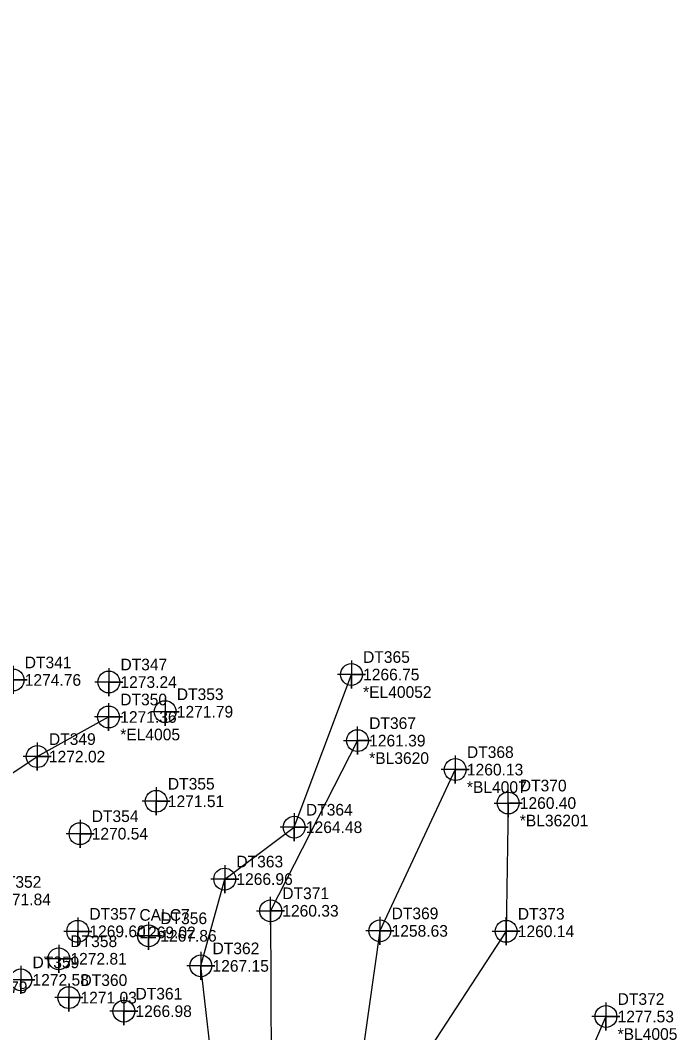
# Model space of a CAD drawing. Extents: x 1391270 to 1392151, y 960049 to 960667.
# Drawn here: x 1391544.4 to 1391685.2, y 960444.8 to 960661.8 of the extents above; entities that cross this region are included whole.
import ezdxf

# ---------------------------------------------------------------- set-up
doc = ezdxf.new("R2010")
doc.units = 0
for name, color, linetype in [('COGO Default Point Elevation', 7, 'Continuous'), ('COGO Default Point Number', 7, 'Continuous'), ('Exist DTM Breakline', 7, 'Continuous'), ('Exist DTM Breakline Cogo Comment', 7, 'Continuous'), ('Exist DTM Breakline Cogo Elevation', 7, 'Continuous'), ('Exist DTM Breakline Cogo Number', 7, 'Continuous'), ('Exist DTM Breakline Cogo Point CELL', 7, 'Continuous'), ('Exist DTM Breakline Underwater', 7, 'Continuous'), ('Exist DTM Breakline Underwater Cogo Comment', 7, 'Continuous'), ('Exist DTM Breakline Underwater Cogo Elevation', 7, 'Continuous'), ('Exist DTM Breakline Underwater Cogo Number', 7, 'Continuous'), ('Exist DTM Breakline Underwater Cogo Point CELL', 7, 'Continuous'), ('Exist DTM Regular Point CELL', 7, 'Continuous'), ('Exist DTM Regular Point Cogo Elevation', 7, 'Continuous'), ('Exist DTM Regular Point Cogo Number', 7, 'Continuous'), ('Exist Hydro Stream or Body of Water', 7, 'Continuous'), ('Exist Hydro Stream or Body of Water Cogo Comment', 7, 'Continuous'), ('Exist Hydro Stream or Body of Water Cogo Elevation', 7, 'Continuous'), ('Exist Hydro Stream or Body of Water Cogo Number', 7, 'Continuous'), ('Exist Hydro Stream or Body of Water Cogo Point CELL', 7, 'Continuous'), ('Exist Roads EOP', 7, 'Continuous')]:
    doc.layers.add(name, color=color, linetype=linetype)

msp = doc.modelspace()

# ---------------------------------------------------------------- linework, layer by layer
at = {"layer": 'Exist DTM Breakline'}
msp.add_line((1391670.034, 960448.283), (1391658.104, 960420.856), dxfattribs=at)
for points in [[(1391393.449, 960661.814), (1391420.927, 960625.274), (1391436.139, 960609.727), (1391454.255, 960579.709), (1391474.064, 960542.237), (1391491.205, 960517.974), (1391488.925, 960510.22), (1391503.285, 960493.748), (1391518.522, 960484.392), (1391548.09, 960503.995), (1391563.385, 960512.482)], [(1391572.183, 960404.498), (1391585.5, 960391.636), (1391586.242, 960432.256), (1391583.174, 960459.141), (1391588.288, 960477.745), (1391603.196, 960488.857), (1391615.455, 960521.583)]]:
    msp.add_lwpolyline(points, dxfattribs=at)
at = {"layer": 'Exist DTM Breakline Cogo Point CELL'}
for points in [[(1391615.455, 960524.583), (1391615.455, 960518.583), (1391615.455, 960521.583), (1391618.455, 960521.583), (1391612.455, 960521.583)], [(1391563.385, 960515.482), (1391563.385, 960509.482), (1391563.385, 960512.482), (1391566.385, 960512.482), (1391560.385, 960512.482)], [(1391548.09, 960506.995), (1391548.09, 960500.995), (1391548.09, 960503.995), (1391551.09, 960503.995), (1391545.09, 960503.995)], [(1391603.196, 960491.857), (1391603.196, 960485.857), (1391603.196, 960488.857), (1391606.196, 960488.857), (1391600.196, 960488.857)], [(1391588.288, 960480.745), (1391588.288, 960474.745), (1391588.288, 960477.745), (1391591.288, 960477.745), (1391585.288, 960477.745)], [(1391583.174, 960462.141), (1391583.174, 960456.141), (1391583.174, 960459.141), (1391586.174, 960459.141), (1391580.174, 960459.141)], [(1391670.034, 960451.283), (1391670.034, 960445.283), (1391670.034, 960448.283), (1391673.034, 960448.283), (1391667.034, 960448.283)]]:
    msp.add_lwpolyline(points, dxfattribs=at)
for centre in [(1391615.455, 960521.583), (1391563.385, 960512.482), (1391548.09, 960503.995), (1391603.196, 960488.857), (1391588.288, 960477.745), (1391583.174, 960459.141), (1391670.034, 960448.283)]:
    msp.add_circle(centre, 2.344, dxfattribs=at)
at = {"layer": 'Exist DTM Breakline Underwater'}
msp.add_lwpolyline([(1391637.721, 960501.208), (1391621.569, 960466.64), (1391617.066, 960434.832), (1391615.14, 960379.594), (1391599.785, 960319.127), (1391597.418, 960292.355)], dxfattribs=at)
at = {"layer": 'Exist DTM Breakline Underwater Cogo Point CELL'}
for points in [[(1391637.721, 960504.208), (1391637.721, 960498.208), (1391637.721, 960501.208), (1391640.721, 960501.208), (1391634.721, 960501.208)], [(1391621.569, 960469.64), (1391621.569, 960463.64), (1391621.569, 960466.64), (1391624.569, 960466.64), (1391618.569, 960466.64)]]:
    msp.add_lwpolyline(points, dxfattribs=at)
for centre in [(1391637.721, 960501.208), (1391621.569, 960466.64)]:
    msp.add_circle(centre, 2.344, dxfattribs=at)
at = {"layer": 'Exist DTM Regular Point CELL'}
for points in [[(1391542.901, 960523.419), (1391542.901, 960517.419), (1391542.901, 960520.419), (1391545.901, 960520.419), (1391539.901, 960520.419)], [(1391563.428, 960522.975), (1391563.428, 960516.975), (1391563.428, 960519.975), (1391566.428, 960519.975), (1391560.428, 960519.975)], [(1391575.51, 960516.618), (1391575.51, 960510.618), (1391575.51, 960513.618), (1391578.51, 960513.618), (1391572.51, 960513.618)], [(1391573.596, 960497.418), (1391573.596, 960491.418), (1391573.596, 960494.418), (1391576.596, 960494.418), (1391570.596, 960494.418)], [(1391557.265, 960490.475), (1391557.265, 960484.475), (1391557.265, 960487.475), (1391560.265, 960487.475), (1391554.265, 960487.475)], [(1391556.764, 960469.542), (1391556.764, 960463.542), (1391556.764, 960466.542), (1391559.764, 960466.542), (1391553.764, 960466.542)], [(1391571.974, 960468.583), (1391571.974, 960462.583), (1391571.974, 960465.583), (1391574.974, 960465.583), (1391568.974, 960465.583)], [(1391552.697, 960463.664), (1391552.697, 960457.664), (1391552.697, 960460.664), (1391555.697, 960460.664), (1391549.697, 960460.664)], [(1391544.57, 960459.148), (1391544.57, 960453.148), (1391544.57, 960456.148), (1391547.57, 960456.148), (1391541.57, 960456.148)], [(1391554.859, 960455.34), (1391554.859, 960449.34), (1391554.859, 960452.34), (1391557.859, 960452.34), (1391551.859, 960452.34)], [(1391566.651, 960452.432), (1391566.651, 960446.432), (1391566.651, 960449.432), (1391569.651, 960449.432), (1391563.651, 960449.432)]]:
    msp.add_lwpolyline(points, dxfattribs=at)
for centre in [(1391542.901, 960520.419), (1391563.428, 960519.975), (1391575.51, 960513.618), (1391573.596, 960494.418), (1391557.265, 960487.475), (1391556.764, 960466.542), (1391571.974, 960465.583), (1391552.697, 960460.664), (1391544.57, 960456.148), (1391554.859, 960452.34), (1391566.651, 960449.432)]:
    msp.add_circle(centre, 2.344, dxfattribs=at)
at = {"layer": 'Exist Hydro Stream or Body of Water'}
for points in [[(1391616.765, 960507.42), (1391598.132, 960470.947), (1391598.223, 960437.776), (1391598.007, 960414.172), (1391597.194, 960388.554), (1391588.85, 960350.646), (1391564.84, 960352.852), (1391552.616, 960357.272), (1391528.84, 960367.287), (1391524.75, 960364.767)], [(1391649.062, 960494.038), (1391648.634, 960466.546), (1391627.196, 960433.7), (1391623.135, 960411.167), (1391625.85, 960360.364), (1391618.453, 960319.772), (1391609.949, 960287.686), (1391599.63, 960231.778)]]:
    msp.add_lwpolyline(points, dxfattribs=at)
at = {"layer": 'Exist Hydro Stream or Body of Water Cogo Point CELL'}
for points in [[(1391613.765, 960507.42), (1391619.765, 960507.42), (1391616.765, 960507.42), (1391616.765, 960504.42), (1391616.765, 960510.42)], [(1391646.062, 960494.038), (1391652.062, 960494.038), (1391649.062, 960494.038), (1391649.062, 960491.038), (1391649.062, 960497.038)], [(1391595.132, 960470.947), (1391601.132, 960470.947), (1391598.132, 960470.947), (1391598.132, 960467.947), (1391598.132, 960473.947)], [(1391645.634, 960466.546), (1391651.634, 960466.546), (1391648.634, 960466.546), (1391648.634, 960463.546), (1391648.634, 960469.546)]]:
    msp.add_lwpolyline(points, dxfattribs=at)
for centre in [(1391616.765, 960507.42), (1391649.062, 960494.038), (1391598.132, 960470.947), (1391648.634, 960466.546)]:
    msp.add_circle(centre, 2.344, dxfattribs=at)
at = {"layer": 'Exist Roads EOP'}
msp.add_spline([(1391558.507, 960409.653), (1391527.113, 960438.384), (1391489.556, 960472.216), (1391453.007, 960506.097), (1391416.783, 960539.246), (1391379.565, 960572.597), (1391343.959, 960605.485)], degree=3, dxfattribs=at)

# ---------------------------------------------------------------- texts
at = {"layer": 'COGO Default Point Elevation'}
msp.add_text('1269.02', height=2.5, dxfattribs=at).set_placement((1391569.993, 960465.06))
at = {"layer": 'COGO Default Point Number'}
msp.add_text('CALC7', height=2.5, dxfattribs=at).set_placement((1391569.993, 960468.81))
at = {"layer": 'Exist DTM Breakline Cogo Comment'}
for s, p in [('*EL40052', (1391617.955, 960516.583)), ('*EL4005', (1391565.885, 960507.482)), ('*BL4005', (1391672.534, 960443.283))]:
    msp.add_text(s, height=2.5, dxfattribs=at).set_placement(p)
at = {"layer": 'Exist DTM Breakline Cogo Elevation'}
for s, p in [('1266.75', (1391617.955, 960520.333)), ('1271.36', (1391565.885, 960511.232)), ('1272.02', (1391550.59, 960502.745)), ('1264.48', (1391605.696, 960487.607)), ('1266.96', (1391590.788, 960476.495)), ('1267.15', (1391585.674, 960457.891)), ('1271.79', (1391533.904, 960453.303)), ('1277.53', (1391672.534, 960447.033))]:
    msp.add_text(s, height=2.5, dxfattribs=at).set_placement(p)
at = {"layer": 'Exist DTM Breakline Cogo Number'}
for s, p in [('DT365', (1391617.955, 960524.083)), ('DT350', (1391565.885, 960514.982)), ('DT349', (1391550.59, 960506.495)), ('DT364', (1391605.696, 960491.357)), ('DT363', (1391590.788, 960480.245)), ('DT362', (1391585.674, 960461.641)), ('DT372', (1391672.534, 960450.783))]:
    msp.add_text(s, height=2.5, dxfattribs=at).set_placement(p)
at = {"layer": 'Exist DTM Breakline Underwater Cogo Comment'}
msp.add_text('*BL4007', height=2.5, dxfattribs=at).set_placement((1391640.221, 960496.208))
at = {"layer": 'Exist DTM Breakline Underwater Cogo Elevation'}
for s, p in [('1260.13', (1391640.221, 960499.958)), ('1258.63', (1391624.069, 960465.39))]:
    msp.add_text(s, height=2.5, dxfattribs=at).set_placement(p)
at = {"layer": 'Exist DTM Breakline Underwater Cogo Number'}
for s, p in [('DT368', (1391640.221, 960503.708)), ('DT369', (1391624.069, 960469.14))]:
    msp.add_text(s, height=2.5, dxfattribs=at).set_placement(p)
at = {"layer": 'Exist DTM Regular Point Cogo Elevation'}
for s, p in [('1274.76', (1391545.401, 960519.169)), ('1273.24', (1391565.928, 960518.725)), ('1271.79', (1391578.01, 960512.368)), ('1271.51', (1391576.096, 960493.168)), ('1270.54', (1391559.765, 960486.225)), ('1271.84', (1391538.937, 960472.131)), ('1269.60', (1391559.264, 960465.292)), ('1267.86', (1391574.474, 960464.333)), ('1272.81', (1391555.197, 960459.414)), ('1272.58', (1391547.07, 960454.898)), ('1271.03', (1391557.359, 960451.09)), ('1266.98', (1391569.151, 960448.182))]:
    msp.add_text(s, height=2.5, dxfattribs=at).set_placement(p)
at = {"layer": 'Exist DTM Regular Point Cogo Number'}
for s, p in [('DT341', (1391545.401, 960522.919)), ('DT347', (1391565.928, 960522.475)), ('DT353', (1391578.01, 960516.118)), ('DT355', (1391576.096, 960496.918)), ('DT354', (1391559.765, 960489.975)), ('DT352', (1391538.937, 960475.881)), ('DT357', (1391559.264, 960469.042)), ('DT356', (1391574.474, 960468.083)), ('DT358', (1391555.197, 960463.164)), ('DT359', (1391547.07, 960458.648)), ('DT360', (1391557.359, 960454.84)), ('DT361', (1391569.151, 960451.932))]:
    msp.add_text(s, height=2.5, dxfattribs=at).set_placement(p)
at = {"layer": 'Exist Hydro Stream or Body of Water Cogo Comment'}
for s, p in [('*BL3620', (1391619.265, 960502.42)), ('*BL36201', (1391651.562, 960489.038))]:
    msp.add_text(s, height=2.5, dxfattribs=at).set_placement(p)
at = {"layer": 'Exist Hydro Stream or Body of Water Cogo Elevation'}
for s, p in [('1261.39', (1391619.265, 960506.17)), ('1260.40', (1391651.562, 960492.788)), ('1260.33', (1391600.632, 960469.697)), ('1260.14', (1391651.134, 960465.296))]:
    msp.add_text(s, height=2.5, dxfattribs=at).set_placement(p)
at = {"layer": 'Exist Hydro Stream or Body of Water Cogo Number'}
for s, p in [('DT367', (1391619.265, 960509.92)), ('DT370', (1391651.562, 960496.538)), ('DT371', (1391600.632, 960473.447)), ('DT373', (1391651.134, 960469.046))]:
    msp.add_text(s, height=2.5, dxfattribs=at).set_placement(p)

doc.saveas('drawing.dxf')
